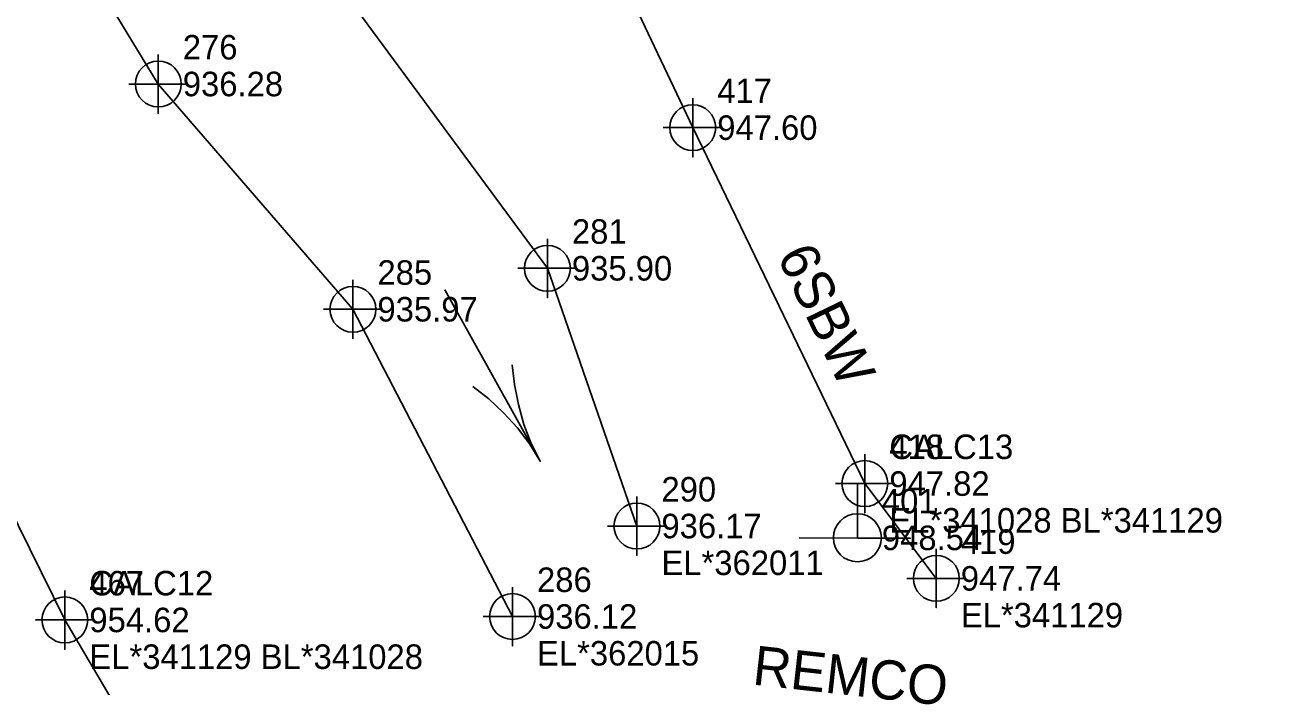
# Model space of a CAD drawing. Extents: x 1150279 to 1151282, y 655434 to 657999.
# Drawn here: x 1150767.1 to 1150895, y 656986.7 to 657054.2 of the extents above; entities that cross this region are included whole.
import ezdxf

# ---------------------------------------------------------------- set-up
doc = ezdxf.new("R2010")
doc.units = 0
for name, color, linetype in [('Exist Hydro Jurisdictional Stream or Body of Water', 7, 'Continuous'), ('Exist Hydro River Flow Arrow CELL', 7, 'Continuous'), ('Exist Hydro Stream or Body of Water Cogo Comment', 7, 'Continuous'), ('Exist Hydro Stream or Body of Water Cogo Elevation', 7, 'Continuous'), ('Exist Hydro Stream or Body of Water Cogo Number', 7, 'Continuous'), ('Exist Hydro Stream or Body of Water Cogo Point CELL', 7, 'Continuous'), ('Exist Other Culture Fence Line', 7, 'Continuous'), ('Exist Other Culture Fence Line Cogo Comment', 7, 'Continuous'), ('Exist Other Culture Fence Line Cogo Elevation', 7, 'Continuous'), ('Exist Other Culture Fence Line Cogo Number', 7, 'Continuous'), ('Exist Other Culture Fence Line Cogo Point CELL', 7, 'Continuous'), ('Exist Other Culture Fence Line Text', 7, 'Continuous'), ('Exist Other Culture Gate', 7, 'Continuous'), ('Exist Other Culture Gate Cogo Comment', 7, 'Continuous'), ('Exist Other Culture Gate Cogo Elevation', 7, 'Continuous'), ('Exist Other Culture Gate Cogo Number', 7, 'Continuous'), ('Exist Other Culture Gate Cogo Point CELL', 7, 'Continuous'), ('Exist Utilities Power Joint Use Telephone CELL', 7, 'Continuous'), ('Exist Utilities Power Joint Use Telephone Cogo Elevation', 7, 'Continuous'), ('Exist Utilities Power Joint Use Telephone Cogo Number', 7, 'Continuous'), ('Exist Utilities Power Joint Use Telephone Text', 7, 'Continuous')]:
    doc.layers.add(name, color=color, linetype=linetype)

msp = doc.modelspace()

# ---------------------------------------------------------------- linework, layer by layer
at = {"layer": 'Exist Hydro Jurisdictional Stream or Body of Water'}
for points in [[(1150769.35, 657125.31), (1150769.52, 657122.14), (1150780.79, 657091.68), (1150798.34, 657059.3), (1150820.35, 657029.39), (1150829.48, 657003.1)], [(1150745.79, 657124.78), (1150745.93, 657121.28), (1150758.49, 657084.64), (1150780.67, 657048.19), (1150800.52, 657025.21), (1150816.79, 656993.87)]]:
    msp.add_lwpolyline(points, dxfattribs=at)
at = {"layer": 'Exist Hydro River Flow Arrow CELL'}
msp.add_line((1150814.76, 657018.44), (1150814.76, 657018.44), dxfattribs=at)
msp.add_lwpolyline([(1150816.76, 657019.55), (1150816.99, 657017.52), (1150817.39, 657015.49), (1150817.96, 657013.47), (1150818.69, 657011.53), (1150819.62, 657009.7), (1150809.9, 657027.18), (1150819.62, 657009.7), (1150818.56, 657011.46), (1150817.29, 657013.1), (1150815.88, 657014.65), (1150814.37, 657016.06), (1150812.76, 657017.33)], dxfattribs=at)
at = {"layer": 'Exist Hydro Stream or Body of Water Cogo Point CELL'}
for points in [[(1150777.67, 657048.19), (1150783.67, 657048.19), (1150780.67, 657048.19), (1150780.67, 657045.19), (1150780.67, 657051.19)], [(1150817.35, 657029.39), (1150823.35, 657029.39), (1150820.35, 657029.39), (1150820.35, 657026.39), (1150820.35, 657032.39)], [(1150797.52, 657025.21), (1150803.52, 657025.21), (1150800.52, 657025.21), (1150800.52, 657022.21), (1150800.52, 657028.21)], [(1150826.48, 657003.1), (1150832.48, 657003.1), (1150829.48, 657003.1), (1150829.48, 657000.1), (1150829.48, 657006.1)], [(1150813.79, 656993.87), (1150819.79, 656993.87), (1150816.79, 656993.87), (1150816.79, 656990.87), (1150816.79, 656996.87)]]:
    msp.add_lwpolyline(points, dxfattribs=at)
for centre in [(1150780.67, 657048.19), (1150820.35, 657029.39), (1150800.52, 657025.21), (1150829.48, 657003.1), (1150816.79, 656993.87)]:
    msp.add_circle(centre, 2.34, dxfattribs=at)
at = {"layer": 'Exist Other Culture Fence Line'}
for points in [[(1151064.38, 657042.2), (1151035.79, 657039.66), (1150986.53, 657050.15), (1150941.42, 657063.2), (1150898.39, 657078.65), (1150854.86, 657094.99), (1150825.03, 657100.53), (1150812.46, 657091.59), (1150835.17, 657043.74), (1150852.72, 657007.43)], [(1150771.14, 656993.52), (1150752.14, 657032.02), (1150729.28, 657075.13), (1150719.49, 657093.07), (1150693.83, 657099.27)]]:
    msp.add_lwpolyline(points, dxfattribs=at)
at = {"layer": 'Exist Other Culture Fence Line Cogo Point CELL'}
for points in [[(1150835.17, 657046.74), (1150835.17, 657040.74), (1150835.17, 657043.74), (1150838.17, 657043.74), (1150832.17, 657043.74)], [(1150852.72, 657010.43), (1150852.72, 657004.43), (1150852.72, 657007.43), (1150855.72, 657007.43), (1150849.72, 657007.43)], [(1150771.14, 656996.52), (1150771.14, 656990.52), (1150771.14, 656993.52), (1150774.14, 656993.52), (1150768.14, 656993.52)]]:
    msp.add_lwpolyline(points, dxfattribs=at)
for centre in [(1150835.17, 657043.74), (1150852.72, 657007.43), (1150771.14, 656993.52)]:
    msp.add_circle(centre, 2.34, dxfattribs=at)
at = {"layer": 'Exist Other Culture Gate'}
for p, q in [((1150852.72, 657007.43), (1150860.01, 656997.76)), ((1150779.56, 656979.27), (1150771.14, 656993.52))]:
    msp.add_line(p, q, dxfattribs=at)
at = {"layer": 'Exist Other Culture Gate Cogo Point CELL'}
for points in [[(1150852.72, 657010.43), (1150852.72, 657004.43), (1150852.72, 657007.43), (1150855.72, 657007.43), (1150849.72, 657007.43)], [(1150860.01, 657000.76), (1150860.01, 656994.76), (1150860.01, 656997.76), (1150863.01, 656997.76), (1150857.01, 656997.76)], [(1150771.14, 656996.52), (1150771.14, 656990.52), (1150771.14, 656993.52), (1150774.14, 656993.52), (1150768.14, 656993.52)]]:
    msp.add_lwpolyline(points, dxfattribs=at)
for centre in [(1150852.72, 657007.43), (1150860.01, 656997.76), (1150771.14, 656993.52)]:
    msp.add_circle(centre, 2.34, dxfattribs=at)
at = {"layer": 'Exist Utilities Power Joint Use Telephone CELL'}
msp.add_line((1150851.96, 657001.89), (1150851.96, 657001.89), dxfattribs=at)
msp.add_lwpolyline([(1150846.02, 657001.89), (1150857.36, 657001.85), (1150851.96, 657001.87), (1150851.96, 657007.52)], dxfattribs=at)
msp.add_circle((1150851.96, 657001.9), 2.45, dxfattribs=at)

# ---------------------------------------------------------------- texts
at = {"layer": 'Exist Hydro Stream or Body of Water Cogo Comment'}
for s, p in [('EL*362011', (1150831.98, 656998.1)), ('EL*362015', (1150819.29, 656988.87))]:
    msp.add_text(s, height=2.5, dxfattribs=at).set_placement(p)
at = {"layer": 'Exist Hydro Stream or Body of Water Cogo Elevation'}
for s, p in [('936.28', (1150783.17, 657046.94)), ('935.90', (1150822.85, 657028.14)), ('935.97', (1150803.02, 657023.96)), ('936.17', (1150831.98, 657001.85)), ('936.12', (1150819.29, 656992.62))]:
    msp.add_text(s, height=2.5, dxfattribs=at).set_placement(p)
at = {"layer": 'Exist Hydro Stream or Body of Water Cogo Number'}
for s, p in [('276', (1150783.17, 657050.69)), ('281', (1150822.85, 657031.89)), ('285', (1150803.02, 657027.71)), ('290', (1150831.98, 657005.6)), ('286', (1150819.29, 656996.37))]:
    msp.add_text(s, height=2.5, dxfattribs=at).set_placement(p)
at = {"layer": 'Exist Other Culture Fence Line Cogo Comment'}
msp.add_text('EL*341028 BL*341129', height=2.5, dxfattribs=at).set_placement((1150855.22, 657002.43))
at = {"layer": 'Exist Other Culture Fence Line Cogo Elevation'}
for s, p in [('947.60', (1150837.67, 657042.49)), ('947.82', (1150855.22, 657006.18)), ('954.62', (1150773.64, 656992.27))]:
    msp.add_text(s, height=2.5, dxfattribs=at).set_placement(p)
at = {"layer": 'Exist Other Culture Fence Line Cogo Number'}
for s, p in [('417', (1150837.67, 657046.24)), ('418', (1150855.22, 657009.93)), ('CALC12', (1150773.64, 656996.02))]:
    msp.add_text(s, height=2.5, dxfattribs=at).set_placement(p)
at = {"layer": 'Exist Other Culture Fence Line Text'}
msp.add_text('6SBW', height=4, rotation=295.7922, dxfattribs=at).set_placement((1150843.72, 657030.64))
at = {"layer": 'Exist Other Culture Gate Cogo Comment'}
for s, p in [('EL*341129', (1150862.51, 656992.76)), ('EL*341129 BL*341028', (1150773.64, 656988.52))]:
    msp.add_text(s, height=2.5, dxfattribs=at).set_placement(p)
at = {"layer": 'Exist Other Culture Gate Cogo Elevation'}
for s, p in [('947.82', (1150855.22, 657006.18)), ('947.74', (1150862.51, 656996.51)), ('954.62', (1150773.64, 656992.27))]:
    msp.add_text(s, height=2.5, dxfattribs=at).set_placement(p)
at = {"layer": 'Exist Other Culture Gate Cogo Number'}
for s, p in [('CALC13', (1150855.22, 657009.93)), ('419', (1150862.51, 657000.26)), ('467', (1150773.64, 656996.02))]:
    msp.add_text(s, height=2.5, dxfattribs=at).set_placement(p)
at = {"layer": 'Exist Utilities Power Joint Use Telephone Cogo Elevation'}
msp.add_text('948.54', height=2.5, dxfattribs=at).set_placement((1150854.46, 657000.64))
at = {"layer": 'Exist Utilities Power Joint Use Telephone Cogo Number'}
msp.add_text('401', height=2.5, dxfattribs=at).set_placement((1150854.46, 657004.39))
at = {"layer": 'Exist Utilities Power Joint Use Telephone Text'}
msp.add_text('REMCO', height=4, rotation=353.6867, dxfattribs=at).set_placement((1150841.17, 656986.94))

doc.saveas('drawing.dxf')
